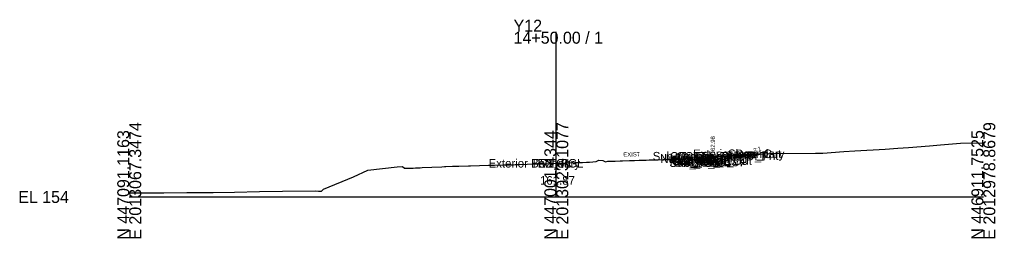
# Model space of a CAD drawing. Extents: x -26 to 1203, y -10 to 9542.
# Drawn here: x -25.7 to 202.8, y 8990.3 to 9041.5 of the extents above; entities that cross this region are included whole.
import ezdxf

# ---------------------------------------------------------------- set-up
doc = ezdxf.new("R2010")
doc.units = 0
for name, color, linetype in [('Default', 7, 'Continuous'), ('Exist Cross Section Cell', 7, 'Continuous'), ('Exist XS Center Line Elevation Label', 7, 'Continuous'), ('Exist XS Ground Line', 7, 'Continuous'), ('Prop CMT Conc Surface', 7, 'Continuous'), ('Prop CMT Concrete Structures', 7, 'Continuous'), ('Prop CMT Pvmt Course 1', 7, 'Continuous'), ('Prop CMT Pvmt Course 1 CG', 7, 'Continuous'), ('Prop CMT Pvmt Course 2', 7, 'Continuous'), ('Prop CMT Pvmt Course 3', 7, 'Continuous'), ('Prop CMT Pvmt Surface', 7, 'Continuous'), ('Prop CMT Slope Grass', 7, 'Continuous'), ('Prop CMT Subgrade Earthwork', 7, 'Continuous'), ('Prop XS Earthwork Shape', 7, 'Continuous'), ('Prop XS Hydro Elevations', 7, 'Continuous'), ('Prop XS SE Text', 7, 'Continuous'), ('Prop XS Side Slope Text', 7, 'Continuous'), ('Scratch_Level_0', 7, 'Continuous')]:
    doc.layers.add(name, color=color, linetype=linetype)

msp = doc.modelspace()

# ---------------------------------------------------------------- linework, layer by layer
at = {"layer": 'Exist Cross Section Cell'}
for p, q in [((100, 9000), (100, 9038.61)), ((0, 9000), (100, 9000)), ((100, 9000), (200, 9000))]:
    msp.add_line(p, q, dxfattribs=at)
at = {"layer": 'Exist XS Ground Line'}
msp.add_lwpolyline([(0, 9000.94), (2.36, 9000.95), (8.08, 9000.96), (13.51, 9001.01), (15.55, 9001.08), (19.69, 9001.08), (24.66, 9001.12), (30.49, 9001.28), (35.85, 9001.38), (43.52, 9001.42), (44.3, 9001.37), (45.02, 9001.32), (45.52, 9001.82), (52.5, 9004.67), (55.88, 9006.28), (62.7, 9007.02), (63.96, 9007.14), (64.49, 9006.73), (64.95, 9006.73), (66.48, 9006.76), (67.04, 9006.79), (68.11, 9006.84), (68.56, 9006.86), (70.87, 9006.95), (73.19, 9007.05), (73.82, 9007.08), (74.16, 9007.09), (75.72, 9007.16), (76.46, 9007.19), (77.21, 9007.21), (79.46, 9007.26), (79.88, 9007.28), (82.03, 9007.34), (84.12, 9007.39), (84.82, 9007.4), (85.53, 9007.42), (87.47, 9007.48), (87.91, 9007.49), (89.97, 9007.54), (90.37, 9007.55), (91.16, 9007.58), (93.15, 9007.65), (95.08, 9007.72), (95.92, 9007.74), (96.79, 9007.77), (98.47, 9007.82), (98.93, 9007.84), (100, 9007.87), (101.5, 9007.92), (102.41, 9007.95), (104.31, 9008.02), (106.16, 9008.08), (107.09, 9008.12), (107.77, 9008.15), (109.34, 9008.27), (109.94, 9008.57), (110.93, 9008.54), (111.53, 9008.24), (112.04, 9008.36), (112.73, 9008.37), (113.78, 9008.4), (114.92, 9008.43), (115.48, 9008.45), (117.16, 9008.5), (118.28, 9008.53), (119.41, 9008.57), (121.05, 9008.63), (121.77, 9008.66), (122.45, 9008.68), (123.83, 9008.71), (125.05, 9008.74), (126.6, 9008.78), (128.1, 9008.82), (129.38, 9008.85), (129.82, 9008.86), (130.72, 9008.88), (132.14, 9008.92), (132.56, 9008.93), (133.38, 9008.95), (134.73, 9008.97), (135.14, 9008.98), (135.85, 9009.42), (142.88, 9009.79), (149.97, 9010.19), (160.73, 9010.24), (162.39, 9010.26), (167.35, 9010.6), (169.89, 9010.75), (177.04, 9011.2), (179.98, 9011.4), (182.47, 9011.56), (187.4, 9011.97), (189.97, 9012.2), (194.68, 9012.54), (200, 9012.66)], dxfattribs=at)
at = {"layer": 'Prop CMT Conc Surface'}
msp.add_lwpolyline([(134.66, 9009), (136.66, 9008.98), (136.66, 9009.48), (137.16, 9009.48)], dxfattribs=at)
at = {"layer": 'Prop CMT Concrete Structures'}
for points in [[(134.66, 9009), (136.66, 9008.98), (136.66, 9009.48), (137.16, 9009.48)], [(137.16, 9009.48), (137.16, 9008.49), (134.66, 9008.41)], [(134.66, 9008.41), (134.66, 9009)]]:
    msp.add_lwpolyline(points, dxfattribs=at)
at = {"layer": 'Prop CMT Pvmt Course 1'}
for points in [[(132.65, 9008.93), (134.66, 9009)], [(132.65, 9008.93), (132.65, 9008.93)], [(132.65, 9008.68), (132.65, 9008.93)], [(134.66, 9009), (134.66, 9008.75)], [(100, 9007.87), (100, 9007.87)], [(134.66, 9008.75), (132.65, 9008.68)]]:
    msp.add_lwpolyline(points, dxfattribs=at)
at = {"layer": 'Prop CMT Pvmt Course 1 CG'}
for points in [[(134.66, 9008.41), (137.66, 9008.51), (137.99, 9008.19)], [(134.66, 9008.08), (134.66, 9008.41)], [(137.99, 9008.19), (134.66, 9008.08)]]:
    msp.add_lwpolyline(points, dxfattribs=at)
at = {"layer": 'Prop CMT Pvmt Course 2'}
for points in [[(132.65, 9008.68), (134.66, 9008.75)], [(132.65, 9008.35), (132.65, 9008.68)], [(134.66, 9008.41), (132.65, 9008.35)], [(134.66, 9008.75), (134.66, 9008.41)]]:
    msp.add_lwpolyline(points, dxfattribs=at)
at = {"layer": 'Prop CMT Pvmt Course 3'}
for points in [[(132.65, 9008.35), (134.66, 9008.41)], [(132.65, 9008.01), (132.65, 9008.35)], [(134.66, 9008.08), (132.65, 9008.01)], [(134.66, 9008.41), (134.66, 9008.08)]]:
    msp.add_lwpolyline(points, dxfattribs=at)
at = {"layer": 'Prop CMT Pvmt Surface'}
msp.add_lwpolyline([(132.65, 9008.93), (134.66, 9009)], dxfattribs=at)
at = {"layer": 'Prop CMT Slope Grass'}
msp.add_lwpolyline([(137.16, 9009.48), (146.66, 9009.67), (147.88, 9010.08)], dxfattribs=at)
at = {"layer": 'Prop CMT Subgrade Earthwork'}
for points in [[(132.65, 9008.01), (132.65, 9008.93)], [(134.66, 9008.08), (137.99, 9008.19), (139.32, 9009.52)], [(132.65, 9008.01), (134.66, 9008.08)], [(134.66, 9008.08), (132.65, 9008.01)]]:
    msp.add_lwpolyline(points, dxfattribs=at)
at = {"layer": 'Prop XS Earthwork Shape'}
for points in [[(132.65, 9008.01), (134.66, 9008.08), (137.99, 9008.19), (139.32, 9009.52), (137.16, 9009.48), (137.16, 9008.49), (134.66, 9008.41), (134.66, 9008.97), (133.38, 9008.95), (132.65, 9008.93)], [(135.14, 9008.98), (135.15, 9008.99), (136.66, 9008.98), (136.66, 9009.46), (137.03, 9009.48), (137.16, 9009.48), (137.16, 9008.49), (134.66, 9008.41), (134.66, 9008.97), (134.73, 9008.97)], [(135.15, 9008.99), (135.85, 9009.42), (136.66, 9009.46), (136.66, 9008.98)], [(139.32, 9009.52), (146.66, 9009.67), (147.88, 9010.08), (142.88, 9009.79), (137.16, 9009.48)]]:
    msp.add_lwpolyline(points, close=True, dxfattribs=at)

# ---------------------------------------------------------------- texts
at = {"layer": 'Default'}
msp.add_text('-', height=0.0001, dxfattribs=at).set_placement((0, 9000))
at = {"layer": 'Exist Cross Section Cell'}
for s, p in [('Y12', (90, 9038.61)), ('14+50.00 / 1', (90, 9035.81)), ('EL 154', (-26, 8998.6))]:
    msp.add_text(s, height=2.8, dxfattribs=at).set_placement(p)
for s, p in [('E 2013067.3474', (2.8, 8990)), ('E 2013023.1077', (102.8, 8990)), ('E 2012978.8679', (202.8, 8990)), ('N 447091.1163', (0, 8990)), ('N 447001.4344', (100, 8990)), ('N 446911.7525', (200, 8990))]:
    msp.add_text(s, height=2.8, rotation=90, dxfattribs=at).set_placement(p)
at = {"layer": 'Exist XS Center Line Elevation Label'}
msp.add_text('161.87', height=2, dxfattribs=at).set_placement((96.18, 9002.87))
at = {"layer": 'Prop XS Hydro Elevations'}
msp.add_text('162.98', height=1, rotation=90, dxfattribs=at).set_placement((137.16, 9009.98))
at = {"layer": 'Prop XS SE Text'}
msp.add_text('EXIST', height=1, rotation=1.8605, dxfattribs=at).set_placement((115.71, 9009.38))
at = {"layer": 'Prop XS Side Slope Text'}
msp.add_text('3:1', height=1, rotation=18.4349, dxfattribs=at).set_placement((146.28, 9010.33))
at = {"layer": 'Scratch_Level_0'}
for s, p in [('Exterior Boundary', (132.02, 9009.08)), ('Slope_Cut', (140.21, 9009.08)), ('Exterior Boundary', (84.14, 9006.87)), ('PV1_PGL', (94.47, 9006.87)), ('EX CL', (95.67, 9006.87)), ('Sub_Trench_Out_DLT', (122.58, 9008.52)), ('Null Ex EOP', (124.35, 9007.93)), ('Sub_PGL', (126.46, 9007.01)), ('CG_Top_Face', (126.62, 9008.48)), ('PV2_PGL', (126.56, 9007.68)), ('PV3_PGL', (126.56, 9007.35)), ('CG1_Shelf_Out', (126.91, 9007.51)), ('CG_Bot_IE', (127.27, 9007.41)), ('Sub_OEOT', (127.43, 9007.08)), ('CG_Top_Gut', (127.59, 9007.98)), ('PV2_OEOT', (127.53, 9007.75)), ('PV3_OEOT', (127.53, 9007.41)), ('CG_Top_BOC', (128.14, 9008.48)), ('CG_Bot_BOC', (128.17, 9007.49)), ('PV1_OEOT', (128.1, 9008)), ('Sub_OEOP', (130.79, 9007.19)), ('PV1', (130.73, 9007.93)), ('CSLP_Pnt', (139.53, 9008.67))]:
    msp.add_text(s, height=2, dxfattribs=at).set_placement(p)

doc.saveas('drawing.dxf')
